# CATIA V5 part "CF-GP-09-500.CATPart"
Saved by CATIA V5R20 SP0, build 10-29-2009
Part number: CF-GP-09-500
Definition: NONE
Nomenclature: CF-GP-09-500
Source: Unknown
Description: CF-GP-09-500
Bounding box of the stored display mesh (mm): x 0 to 500, y 0 to 9, z -11 to 11
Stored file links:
  C:\Users\Utente\Desktop\IO LAVORO\3D X SITO CF\X SITO\PLASTICA\CF-GP\CF-GP-09-500.CATPart
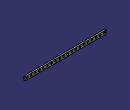
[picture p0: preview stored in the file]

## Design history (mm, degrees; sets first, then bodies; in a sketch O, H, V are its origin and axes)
Body1 "CF-GP-09-500" (main body)
  Solid1: solid without history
